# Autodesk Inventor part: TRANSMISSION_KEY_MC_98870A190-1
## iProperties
Created: 2008-11
Part Number: TRANSMISSION_KEY_MC_98870A190-1
Document SubType Name: Modeling
Designer: ETUDIANT
Author: ETUDIANT
Norme de conversion: STEP AP214IS
Nom du fichier: TRANSMISSION_KEY_MC_98870A190.STEP
Préprocesseur: SolidWorks 2008
Postprocesseur: Build: 344a, Release: 11 SP2 - Date: Fri 08/18/2006
Unités envoyées: INCHES
Incertitude: 1e-05
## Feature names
1. Base1
